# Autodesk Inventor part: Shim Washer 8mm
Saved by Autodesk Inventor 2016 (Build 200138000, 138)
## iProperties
Created: 2015-11
Part Number: Shim Washer 8mm
Material: Generic
Document SubType Name: Modeling
Designer: John
Density: 1 g/cm^3
Appearance: Default
Author: John
Revision Number: ANY
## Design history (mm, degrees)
feature "Boss-Extrude1"
body "Solid1"
